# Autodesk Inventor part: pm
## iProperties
Shininess: 64.0
Length Units: 11269
Angle Units: 11279
Time Units: 11290
Mass Units: 11283
Length Display Precision: 3
Angle Display Precision: 2
Compacted: True
Part Number: pm
Document SubType Name: Modeling
Created: 2004-07
Designer: Peter
Manufacturer: Standard
Standards Organization: Custom
Density: 0.0
Volumn: 0.0
Area: 0.0
PropertySet Name: Model Information
Control State: 0
Master: False
Checked Out: False
Author: Peter
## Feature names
1. Revolution1
